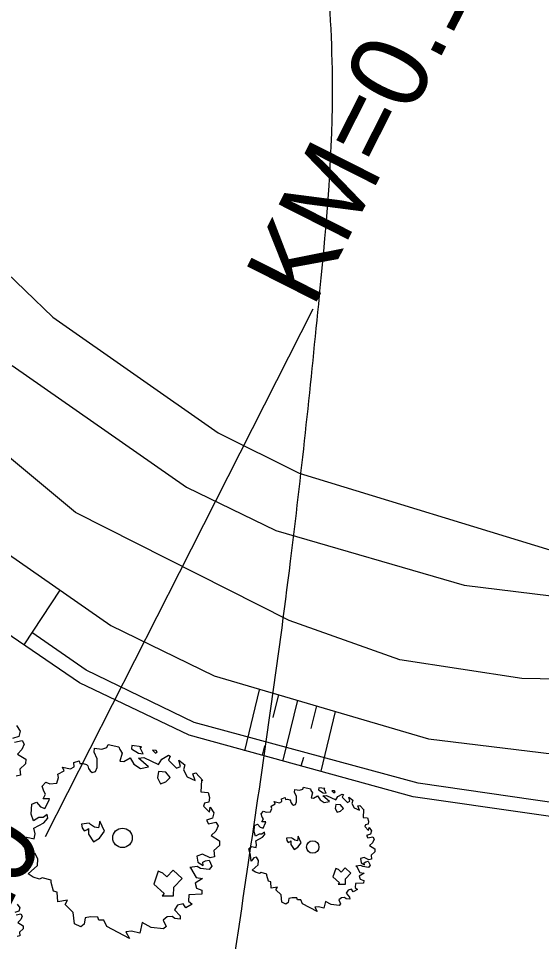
# Model space of a CAD drawing. Extents: x -478102 to -473059, y -1117705 to -1114104.
# Drawn here: x -476391.73 to -476378.48, y -1117058.58 to -1117035.17 of the extents above; entities that cross this region are included whole.
import ezdxf

# ---------------------------------------------------------------- set-up
doc = ezdxf.new("R2010")
doc.units = 0
for name, color, linetype in [('cestn___p____kop', 7, 'Continuous'), ('cesty', 7, 'Continuous'), ('IP', 7, 'Continuous'), ('POLYGONY_SITUACE_PF', 7, 'Continuous'), ('POLYGONY_SITUACE_PF_POPISY', 7, 'Continuous'), ('POLYGONY_SITUACE_PO', 7, 'Continuous'), ('TP _navrh', 7, 'Continuous'), ('Vrstevnice_vedlejsi', 7, 'Continuous')]:
    doc.layers.add(name, color=color, linetype=linetype)

msp = doc.modelspace()

# ---------------------------------------------------------------- linework, layer by layer
at = {"layer": 'cestn___p____kop'}
for p, q in [((-476385.625, -1117052.197), (-476386.003, -1117053.748)), ((-476385.139, -1117052.316), (-476385.281, -1117052.898)), ((-476384.66, -1117052.461), (-476385.031, -1117053.985)), ((-476384.179, -1117052.602), (-476384.32, -1117053.178)), ((-476383.699, -1117052.744), (-476384.068, -1117054.257)), ((-476385.546, -1117053.855), (-476385.481, -1117053.621)), ((-476384.565, -1117054.13), (-476384.501, -1117053.905))]:
    msp.add_line(p, q, dxfattribs=at)
at = {"layer": 'cesty'}
for p, q in [((-476392.856, -1117040.821), (-476390.854, -1117042.749)), ((-476390.854, -1117042.749), (-476386.669, -1117045.683)), ((-476391.887, -1117043.975), (-476387.465, -1117047.062)), ((-476386.669, -1117045.683), (-476384.615, -1117046.705)), ((-476384.615, -1117046.705), (-476377.661, -1117048.832)), ((-476394.517, -1117046.989), (-476389.388, -1117050.569)), ((-476387.465, -1117047.062), (-476385.206, -1117048.156)), ((-476389.388, -1117050.569), (-476386.767, -1117051.839)), ((-476390.009, -1117051.702), (-476391.383, -1117050.743)), ((-476387.271, -1117053.028), (-476390.009, -1117051.702))]:
    msp.add_line(p, q, dxfattribs=at)
for points in [[(-476390.183, -1117052.02), (-476395.648, -1117048.285)], [(-476385.206, -1117048.156), (-476380.435, -1117049.547), (-476375.618, -1117050.138)], [(-476386.767, -1117051.839), (-476381.336, -1117053.441), (-476375.645, -1117054.138)], [(-476387.404, -1117053.344), (-476390.183, -1117052.02)], [(-476375.653, -1117055.43), (-476381.601, -1117054.563), (-476387.271, -1117053.028)], [(-476375.656, -1117055.787), (-476381.727, -1117054.916), (-476387.404, -1117053.344)]]:
    msp.add_lwpolyline(points, dxfattribs=at)
at = {"layer": 'IP'}
for points in [[(-476391.776, -1117053.105), (-476391.683, -1117053.247), (-476391.72, -1117053.381), (-476391.873, -1117053.432)], [(-476391.826, -1117053.526), (-476391.633, -1117053.484), (-476391.578, -1117053.577), (-476391.637, -1117053.713), (-476391.754, -1117053.827), (-476391.542, -1117053.955), (-476391.546, -1117054.078), (-476391.688, -1117054.207), (-476391.674, -1117054.362), (-476391.781, -1117054.386)], [(-476391.755, -1117057.634), (-476391.695, -1117057.725), (-476391.719, -1117057.811), (-476391.817, -1117057.844)], [(-476391.786, -1117057.904), (-476391.663, -1117057.877), (-476391.628, -1117057.937), (-476391.665, -1117058.024), (-476391.741, -1117058.097), (-476391.605, -1117058.18), (-476391.607, -1117058.258), (-476391.699, -1117058.341), (-476391.689, -1117058.441), (-476391.758, -1117058.456)]]:
    msp.add_lwpolyline(points, dxfattribs=at)
for points in [[(-476387.661, -1117053.984), (-476387.512, -1117054.098), (-476387.547, -1117054.227), (-476387.455, -1117054.403), (-476387.246, -1117054.499), (-476387.312, -1117054.328), (-476387.234, -1117054.304), (-476387.055, -1117054.497), (-476387.09, -1117054.486), (-476387.104, -1117054.782), (-476386.922, -1117054.802), (-476386.883, -1117054.932), (-476386.905, -1117055.05), (-476387.01, -1117055.074), (-476387.039, -1117055.145), (-476386.888, -1117055.298), (-476386.866, -1117055.174), (-476386.774, -1117055.316), (-476386.81, -1117055.451), (-476386.963, -1117055.501), (-476386.916, -1117055.595), (-476386.723, -1117055.553), (-476386.669, -1117055.646), (-476386.727, -1117055.783), (-476386.845, -1117055.896), (-476386.633, -1117056.025), (-476386.637, -1117056.147), (-476386.779, -1117056.276), (-476386.764, -1117056.431), (-476386.872, -1117056.455), (-476387.063, -1117056.364), (-476387.207, -1117056.413), (-476387.182, -1117056.571), (-476387.046, -1117056.656), (-476387.057, -1117056.572), (-476386.989, -1117056.534), (-476386.899, -1117056.516), (-476386.827, -1117056.669), (-476386.892, -1117056.758), (-476387.117, -1117056.728), (-476387.195, -1117056.677), (-476387.386, -1117056.704), (-476387.366, -1117056.712), (-476387.225, -1117056.961), (-476387.062, -1117056.982), (-476387.25, -1117057.105), (-476387.213, -1117057.226), (-476387.079, -1117057.282), (-476387.082, -1117057.38), (-476387.408, -1117057.396), (-476387.415, -1117057.556), (-476387.324, -1117057.633), (-476387.487, -1117057.727), (-476387.556, -1117057.626), (-476387.693, -1117057.658), (-476387.774, -1117057.781), (-476387.632, -1117057.929), (-476387.631, -1117058.016), (-476387.766, -1117057.996), (-476387.836, -1117057.95), (-476387.957, -1117057.955), (-476388.064, -1117058.038), (-476387.987, -1117058.197), (-476388.053, -1117058.258), (-476388.363, -1117058.225), (-476388.592, -1117058.103), (-476388.652, -1117058.373), (-476388.86, -1117058.318), (-476389.006, -1117058.335), (-476388.913, -1117058.503), (-476389.49, -1117058.204), (-476389.56, -1117058.042), (-476389.689, -1117058.036), (-476389.716, -1117057.961), (-476389.897, -1117057.957), (-476390.034, -1117057.984), (-476390.064, -1117058.141), (-476390.15, -1117058.211), (-476390.306, -1117058.131), (-476390.338, -1117057.847), (-476390.546, -1117057.645), (-476390.486, -1117057.533), (-476390.73, -1117057.578), (-476390.747, -1117057.333), (-476390.836, -1117057.306), (-476390.899, -1117057.082), (-476390.898, -1117057.029), (-476391.129, -1117056.966), (-476391.195, -1117057.004), (-476391.353, -1117056.946), (-476391.479, -1117056.865), (-476391.243, -1117056.655), (-476391.237, -1117056.489), (-476391.305, -1117056.346), (-476391.414, -1117056.381), (-476391.521, -1117056.508), (-476391.551, -1117056.27), (-476391.611, -1117056.023), (-476391.514, -1117055.936), (-476391.325, -1117055.977), (-476391.306, -1117055.854), (-476391.338, -1117055.703), (-476391.08, -1117055.569), (-476390.983, -1117055.455), (-476391, -1117055.361), (-476391.098, -1117055.438), (-476391.212, -1117055.438), (-476391.347, -1117055.522), (-476391.401, -1117055.348), (-476391.386, -1117055.095), (-476391.266, -1117055.047), (-476391.164, -1117055.167), (-476391.054, -1117055.207), (-476390.952, -1117054.997), (-476390.942, -1117054.961), (-476391.097, -1117054.959), (-476391.038, -1117054.841), (-476391.083, -1117054.768), (-476391.126, -1117054.638), (-476391.036, -1117054.536), (-476390.933, -1117054.58), (-476390.755, -1117054.563), (-476390.71, -1117054.424), (-476390.728, -1117054.338), (-476390.57, -1117054.25), (-476390.611, -1117054.157), (-476390.406, -1117054.2), (-476390.314, -1117054.148), (-476390.319, -1117054.044), (-476390.184, -1117053.999), (-476390.17, -1117054.069), (-476390.088, -1117054.063), (-476390.001, -1117054.089), (-476389.966, -1117054.127), (-476389.952, -1117054.193), (-476389.909, -1117054.253), (-476389.855, -1117054.295), (-476389.772, -1117054.271), (-476389.736, -1117054.171), (-476389.735, -1117053.951), (-476389.808, -1117053.781), (-476389.799, -1117053.676), (-476389.617, -1117053.707), (-476389.487, -1117053.662), (-476389.456, -1117053.584), (-476389.183, -1117053.645), (-476389.161, -1117053.713), (-476389.099, -1117053.808), (-476389.154, -1117054.006), (-476389.056, -1117054.014), (-476388.9, -1117053.926), (-476388.802, -1117054.084), (-476388.636, -1117054.194), (-476388.434, -1117054.151), (-476388.688, -1117053.928), (-476388.553, -1117053.916), (-476388.176, -1117054.093), (-476388.094, -1117053.958), (-476387.925, -1117053.858), (-476387.88, -1117053.878), (-476387.928, -1117053.982), (-476387.72, -1117054.186), (-476387.624, -1117054.142)], [(-476388.859, -1117053.693), (-476388.682, -1117053.805), (-476388.567, -1117053.82), (-476388.641, -1117053.666), (-476388.609, -1117053.642), (-476388.857, -1117053.607)], [(-476388.334, -1117053.726), (-476388.258, -1117053.805), (-476388.21, -1117053.767), (-476388.234, -1117053.733)], [(-476388.178, -1117054.273), (-476388.204, -1117054.429), (-476388.127, -1117054.58), (-476387.989, -1117054.528), (-476387.879, -1117054.424), (-476387.993, -1117054.287)], [(-476383.354, -1117054.923), (-476383.259, -1117054.996), (-476383.281, -1117055.078), (-476383.223, -1117055.191), (-476383.088, -1117055.253), (-476383.131, -1117055.143), (-476383.08, -1117055.128), (-476382.966, -1117055.252), (-476382.988, -1117055.245), (-476382.997, -1117055.434), (-476382.88, -1117055.447), (-476382.855, -1117055.53), (-476382.87, -1117055.606), (-476382.937, -1117055.622), (-476382.955, -1117055.667), (-476382.858, -1117055.765), (-476382.845, -1117055.686), (-476382.785, -1117055.777), (-476382.809, -1117055.863), (-476382.907, -1117055.896), (-476382.877, -1117055.956), (-476382.753, -1117055.929), (-476382.718, -1117055.989), (-476382.756, -1117056.076), (-476382.831, -1117056.149), (-476382.695, -1117056.231), (-476382.697, -1117056.31), (-476382.789, -1117056.393), (-476382.779, -1117056.492), (-476382.848, -1117056.508), (-476382.971, -1117056.449), (-476383.063, -1117056.48), (-476383.047, -1117056.582), (-476382.96, -1117056.636), (-476382.967, -1117056.582), (-476382.923, -1117056.558), (-476382.866, -1117056.546), (-476382.819, -1117056.645), (-476382.861, -1117056.702), (-476383.005, -1117056.682), (-476383.055, -1117056.65), (-476383.178, -1117056.667), (-476383.165, -1117056.672), (-476383.075, -1117056.832), (-476382.97, -1117056.846), (-476383.091, -1117056.924), (-476383.067, -1117057.002), (-476382.981, -1117057.038), (-476382.983, -1117057.1), (-476383.192, -1117057.111), (-476383.197, -1117057.213), (-476383.139, -1117057.263), (-476383.243, -1117057.323), (-476383.287, -1117057.258), (-476383.375, -1117057.279), (-476383.427, -1117057.358), (-476383.336, -1117057.453), (-476383.335, -1117057.509), (-476383.421, -1117057.496), (-476383.466, -1117057.466), (-476383.544, -1117057.47), (-476383.613, -1117057.523), (-476383.564, -1117057.625), (-476383.606, -1117057.664), (-476383.805, -1117057.642), (-476383.952, -1117057.564), (-476383.99, -1117057.738), (-476384.123, -1117057.702), (-476384.217, -1117057.713), (-476384.157, -1117057.821), (-476384.528, -1117057.629), (-476384.572, -1117057.525), (-476384.655, -1117057.521), (-476384.673, -1117057.473), (-476384.789, -1117057.471), (-476384.877, -1117057.488), (-476384.895, -1117057.589), (-476384.951, -1117057.633), (-476385.051, -1117057.582), (-476385.071, -1117057.4), (-476385.205, -1117057.271), (-476385.166, -1117057.199), (-476385.323, -1117057.228), (-476385.334, -1117057.071), (-476385.39, -1117057.053), (-476385.431, -1117056.909), (-476385.43, -1117056.875), (-476385.578, -1117056.835), (-476385.621, -1117056.86), (-476385.723, -1117056.822), (-476385.803, -1117056.771), (-476385.652, -1117056.636), (-476385.648, -1117056.529), (-476385.692, -1117056.438), (-476385.761, -1117056.46), (-476385.83, -1117056.542), (-476385.85, -1117056.389), (-476385.888, -1117056.23), (-476385.826, -1117056.175), (-476385.704, -1117056.201), (-476385.692, -1117056.122), (-476385.713, -1117056.025), (-476385.548, -1117055.939), (-476385.485, -1117055.866), (-476385.496, -1117055.806), (-476385.559, -1117055.855), (-476385.632, -1117055.855), (-476385.719, -1117055.909), (-476385.753, -1117055.797), (-476385.744, -1117055.635), (-476385.667, -1117055.604), (-476385.601, -1117055.682), (-476385.531, -1117055.707), (-476385.465, -1117055.572), (-476385.459, -1117055.549), (-476385.558, -1117055.548), (-476385.521, -1117055.472), (-476385.549, -1117055.425), (-476385.577, -1117055.342), (-476385.519, -1117055.276), (-476385.453, -1117055.305), (-476385.339, -1117055.294), (-476385.31, -1117055.205), (-476385.322, -1117055.15), (-476385.22, -1117055.093), (-476385.246, -1117055.034), (-476385.115, -1117055.061), (-476385.056, -1117055.028), (-476385.059, -1117054.961), (-476384.972, -1117054.932), (-476384.964, -1117054.977), (-476384.911, -1117054.973), (-476384.855, -1117054.99), (-476384.833, -1117055.014), (-476384.824, -1117055.057), (-476384.796, -1117055.095), (-476384.762, -1117055.122), (-476384.708, -1117055.107), (-476384.685, -1117055.043), (-476384.684, -1117054.901), (-476384.731, -1117054.792), (-476384.726, -1117054.725), (-476384.609, -1117054.745), (-476384.526, -1117054.716), (-476384.506, -1117054.666), (-476384.331, -1117054.705), (-476384.317, -1117054.749), (-476384.277, -1117054.81), (-476384.312, -1117054.937), (-476384.249, -1117054.942), (-476384.149, -1117054.885), (-476384.086, -1117054.987), (-476383.98, -1117055.057), (-476383.85, -1117055.03), (-476384.013, -1117054.887), (-476383.926, -1117054.879), (-476383.684, -1117054.992), (-476383.632, -1117054.906), (-476383.524, -1117054.842), (-476383.495, -1117054.855), (-476383.525, -1117054.921), (-476383.392, -1117055.052), (-476383.331, -1117055.024)], [(-476384.123, -1117054.736), (-476384.009, -1117054.808), (-476383.935, -1117054.817), (-476383.983, -1117054.719), (-476383.962, -1117054.703), (-476384.121, -1117054.68)], [(-476383.786, -1117054.757), (-476383.737, -1117054.808), (-476383.707, -1117054.784), (-476383.722, -1117054.761)], [(-476383.686, -1117055.108), (-476383.703, -1117055.208), (-476383.653, -1117055.305), (-476383.565, -1117055.272), (-476383.494, -1117055.205), (-476383.567, -1117055.117)], [(-476389.953, -1117055.713), (-476389.953, -1117055.856), (-476389.824, -1117056.057), (-476389.673, -1117055.961), (-476389.545, -1117055.786), (-476389.667, -1117055.526), (-476389.698, -1117055.702), (-476389.801, -1117055.684), (-476389.897, -1117055.614), (-476389.938, -1117055.584), (-476390.126, -1117055.606), (-476390.115, -1117055.7), (-476390.064, -1117055.776), (-476389.992, -1117055.746)], [(-476384.824, -1117056.032), (-476384.824, -1117056.123), (-476384.742, -1117056.252), (-476384.645, -1117056.19), (-476384.563, -1117056.078), (-476384.641, -1117055.912), (-476384.661, -1117056.024), (-476384.727, -1117056.013), (-476384.788, -1117055.968), (-476384.815, -1117055.949), (-476384.935, -1117055.963), (-476384.928, -1117056.023), (-476384.896, -1117056.072), (-476384.849, -1117056.053)], [(-476388.185, -1117056.797), (-476388.298, -1117057.125), (-476388.038, -1117057.366), (-476388.087, -1117057.419), (-476387.797, -1117057.426), (-476387.792, -1117057.206), (-476387.583, -1117056.984), (-476387.805, -1117056.775), (-476387.964, -1117056.945), (-476388.068, -1117056.847)], [(-476383.69, -1117056.727), (-476383.763, -1117056.937), (-476383.596, -1117057.091), (-476383.627, -1117057.126), (-476383.442, -1117057.13), (-476383.438, -1117056.989), (-476383.304, -1117056.847), (-476383.446, -1117056.713), (-476383.549, -1117056.821), (-476383.615, -1117056.759)]]:
    msp.add_lwpolyline(points, close=True, dxfattribs=at)
for centre, radius in [((-476389.09, -1117055.953), 0.247), ((-476384.271, -1117056.185), 0.158)]:
    msp.add_circle(centre, radius, dxfattribs=at)
at = {"layer": 'POLYGONY_SITUACE_PF'}
msp.add_lwpolyline([(-476391.04, -1117055.915), (-476387.65, -1117049.225), (-476384.261, -1117042.534)], dxfattribs=at)
at = {"layer": 'POLYGONY_SITUACE_PO'}
msp.add_lwpolyline([(-476301.427, -1117045.065), (-476372.905, -1117052.019), (-476378.974, -1117051.908), (-476382.069, -1117051.436), (-476384.865, -1117050.444), (-476390.281, -1117047.7), (-476394.946, -1117043.817), (-476398.626, -1117038.989), (-476458.957, -1116938.029), (-476465.394, -1116926.586), (-476471.221, -1116914.82), (-476476.422, -1116902.765), (-476480.983, -1116890.454), (-476499.392, -1116836.452), (-476499.929, -1116834.228), (-476500.052, -1116831.944), (-476499.756, -1116829.676), (-476499.052, -1116827.5), (-476496.647, -1116821.88)], dxfattribs=at)
at = {"layer": 'TP _navrh'}
msp.add_line((-476390.677, -1117049.669), (-476391.59, -1117051.059), dxfattribs=at)
at = {"layer": 'Vrstevnice_vedlejsi'}
for points in [[(-476429.382, -1116802.255), (-476427.577, -1116804.493), (-476426.152, -1116806.848), (-476425.107, -1116809.32), (-476424.442, -1116811.91), (-476423.987, -1116813.812), (-476423.744, -1116815.028), (-476423.711, -1116815.556), (-476423.685, -1116815.983), (-476423.665, -1116816.309), (-476423.653, -1116816.533), (-476423.365, -1116819.955), (-476422.802, -1116826.574), (-476421.964, -1116836.392), (-476420.828, -1116844.21), (-476419.393, -1116850.028), (-476417.658, -1116853.847), (-476415.4, -1116859.181), (-476412.617, -1116866.03), (-476409.309, -1116874.395), (-476407.176, -1116880.263), (-476406.218, -1116883.637), (-476406.434, -1116884.515), (-476405.944, -1116887.374), (-476404.748, -1116892.215), (-476402.846, -1116899.038), (-476401.243, -1116903.921), (-476399.938, -1116906.863), (-476398.934, -1116907.866), (-476397.275, -1116909.125), (-476394.963, -1116910.641), (-476391.996, -1116912.413), (-476390.213, -1116913.967), (-476389.611, -1116915.304), (-476390.193, -1116916.422), (-476390.887, -1116917.801), (-476391.694, -1116919.438), (-476392.614, -1116921.336), (-476393.031, -1116926.229), (-476392.946, -1116934.117), (-476392.357, -1116945.001), (-476391.819, -1116953.244), (-476391.329, -1116958.848), (-476390.889, -1116961.812), (-476390.846, -1116967.295), (-476391.198, -1116975.299), (-476391.947, -1116985.824), (-476392.181, -1116993.785), (-476391.901, -1116999.183), (-476391.105, -1117002.017), (-476389.811, -1117006.894), (-476388.017, -1117013.813), (-476385.723, -1117022.773), (-476384.311, -1117030.528), (-476383.779, -1117037.076), (-476384.129, -1117042.418), (-476384.841, -1117048.939), (-476385.915, -1117056.638), (-476387.35, -1117065.515), (-476388.856, -1117072.405), (-476390.432, -1117077.308), (-476392.079, -1117080.223), (-476393.566, -1117082.614), (-476394.896, -1117084.483), (-476396.066, -1117085.828), (-476397.154, -1117086.924), (-476398.158, -1117087.772), (-476399.079, -1117088.372), (-476401.752, -1117090.16), (-476406.178, -1117093.136), (-476412.357, -1117097.3), (-476418.052, -1117102.136), (-476423.265, -1117107.643), (-476427.995, -1117113.822), (-476432.008, -1117118.372), (-476435.302, -1117121.295), (-476437.878, -1117122.589), (-476440.56, -1117123.926), (-476443.35, -1117125.307), (-476446.245, -1117126.73), (-476448.454, -1117128.002), (-476449.974, -1117129.124), (-476450.808, -1117130.096), (-476452.012, -1117133.139), (-476453.587, -1117138.255), (-476455.534, -1117145.443), (-476456.4, -1117152.564), (-476456.185, -1117159.618), (-476454.889, -1117166.606), (-476452.79, -1117171.269), (-476449.889, -1117173.608), (-476446.185, -1117173.624), (-476443.257, -1117173.694), (-476441.107, -1117173.819), (-476439.733, -1117173.999), (-476438.562, -1117174.121), (-476437.593, -1117174.185)], [(-476312.721, -1117085.051), (-476312.162, -1117082.526), (-476311.913, -1117080.032), (-476311.974, -1117077.572), (-476312.345, -1117075.143), (-476313.383, -1117069.89), (-476315.09, -1117061.81), (-476317.464, -1117050.905), (-476319.053, -1117043.623), (-476319.857, -1117039.964), (-476319.875, -1117039.928), (-476319.898, -1117039.853), (-476319.928, -1117039.738), (-476319.964, -1117039.583), (-476320.808, -1117035.51), (-476322.459, -1117027.518), (-476324.918, -1117015.607), (-476326.714, -1117006.768), (-476327.848, -1117001), (-476328.319, -1116998.302), (-476330.077, -1116993.758), (-476333.121, -1116987.367), (-476337.453, -1116979.13), (-476340.546, -1116971.115), (-476342.399, -1116963.323), (-476343.014, -1116955.754), (-476343.66, -1116949.008), (-476344.337, -1116943.083), (-476345.046, -1116937.98), (-476345.79, -1116933.735), (-476346.568, -1116930.347), (-476347.382, -1116927.816), (-476347.813, -1116924.716), (-476347.859, -1116921.047), (-476347.522, -1116916.807), (-476347.291, -1116913.836), (-476347.165, -1116912.134), (-476347.145, -1116911.7), (-476347.131, -1116911.361), (-476347.123, -1116911.118), (-476347.12, -1116910.97), (-476347.358, -1116910.697), (-476347.835, -1116910.299), (-476348.553, -1116909.776), (-476349.688, -1116908.928), (-476351.241, -1116907.756), (-476353.21, -1116906.259), (-476354.451, -1116904.808), (-476354.966, -1116903.404), (-476354.753, -1116902.045), (-476354.661, -1116900.831), (-476354.691, -1116899.761), (-476354.84, -1116898.834), (-476355.497, -1116897.722), (-476356.66, -1116896.423), (-476358.33, -1116894.938), (-476360.327, -1116893.159), (-476362.652, -1116891.085), (-476365.304, -1116888.717), (-476367.486, -1116886.651), (-476369.2, -1116884.887), (-476370.445, -1116883.425), (-476371.635, -1116881.781), (-476372.771, -1116879.956), (-476373.852, -1116877.948), (-476374.758, -1116876.395), (-476375.49, -1116875.297), (-476376.047, -1116874.654), (-476377.319, -1116871.886), (-476379.306, -1116866.993), (-476382.008, -1116859.976), (-476384.043, -1116854.77), (-476385.41, -1116851.374), (-476386.109, -1116849.788), (-476386.823, -1116848.113), (-476387.55, -1116846.349), (-476388.291, -1116844.496), (-476388.743, -1116843.138), (-476388.908, -1116842.272), (-476388.783, -1116841.901), (-476388.764, -1116840.286), (-476388.848, -1116837.428), (-476389.037, -1116833.326), (-476388.798, -1116828.049), (-476388.13, -1116821.599), (-476388.122, -1116821.535)], [(-476361.641, -1116910.017), (-476360.991, -1116911.137), (-476360.552, -1116912.67), (-476360.323, -1116914.616), (-476360.306, -1116916.973), (-476360.308, -1116918.585), (-476360.329, -1116919.449), (-476360.369, -1116919.567), (-476360.386, -1116919.663), (-476360.38, -1116919.738), (-476360.35, -1116919.79), (-476360.486, -1116921.699), (-476360.787, -1116925.464), (-476361.254, -1116931.086), (-476361.67, -1116935.051), (-476362.037, -1116937.36), (-476362.353, -1116938.012), (-476362.549, -1116938.736), (-476362.623, -1116939.532), (-476362.576, -1116940.398), (-476362.264, -1116942.869), (-476361.686, -1116946.945), (-476360.843, -1116952.626), (-476360.093, -1116958.73), (-476359.435, -1116965.256), (-476358.871, -1116972.204), (-476358.36, -1116977.092), (-476357.904, -1116979.919), (-476357.501, -1116980.685), (-476356.57, -1116984.99), (-476355.11, -1116992.835), (-476353.122, -1117004.219), (-476351.571, -1117012.905), (-476350.455, -1117018.893), (-476349.776, -1117022.183), (-476349.504, -1117027.698), (-476349.639, -1117035.437), (-476350.182, -1117045.4), (-476350.307, -1117053.191), (-476350.012, -1117058.811), (-476349.298, -1117062.259), (-476350.091, -1117065.67), (-476352.39, -1117069.042), (-476356.195, -1117072.377), (-476359.92, -1117076.705), (-476363.566, -1117082.026), (-476367.131, -1117088.339), (-476371.33, -1117094.641), (-476376.164, -1117100.933), (-476381.631, -1117107.213), (-476386.474, -1117112.181), (-476390.692, -1117115.834), (-476394.286, -1117118.174), (-476397.491, -1117120.393), (-476400.306, -1117122.492), (-476402.732, -1117124.472), (-476402.928, -1117127.738), (-476400.894, -1117132.291), (-476396.631, -1117138.131), (-476389.647, -1117141.585), (-476379.944, -1117142.653), (-476367.521, -1117141.334), (-476355.525, -1117141.406), (-476343.957, -1117142.868), (-476332.816, -1117145.722), (-476324.482, -1117147.814), (-476318.952, -1117149.144), (-476316.229, -1117149.714), (-476310.745, -1117150.91), (-476302.502, -1117152.733), (-476291.498, -1117155.183), (-476284.107, -1117156.821), (-476280.33, -1117157.647), (-476280.165, -1117157.662), (-476279.816, -1117157.743), (-476279.284, -1117157.891), (-476278.569, -1117158.106), (-476278.072, -1117158.306), (-476277.796, -1117158.489), (-476277.739, -1117158.657), (-476277.684, -1117158.815), (-476277.629, -1117158.963), (-476277.576, -1117159.102), (-476277.523, -1117159.234), (-476277.472, -1117159.361), (-476277.423, -1117159.482), (-476277.379, -1117159.591), (-476277.34, -1117159.689), (-476277.307, -1117159.775), (-476277.275, -1117159.863), (-476277.243, -1117159.954), (-476277.212, -1117160.046), (-476277.173, -1117160.139), (-476277.129, -1117160.233), (-476277.078, -1117160.326), (-476277.04, -1117160.421), (-476277.015, -1117160.516)]]:
    msp.add_spline(points, degree=3, dxfattribs=at)

# ---------------------------------------------------------------- texts
at = {"layer": 'POLYGONY_SITUACE_PF_POPISY'}
for s, p in [('KM=0.174', (-476384.267, -1117042.545)), ('PF 10', (-476394.255, -1117062.263))]:
    msp.add_text(s, height=1.9765, rotation=63.1343, dxfattribs=at).set_placement(p)

doc.saveas('drawing.dxf')
